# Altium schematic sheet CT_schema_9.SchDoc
size 390 x 385 mm
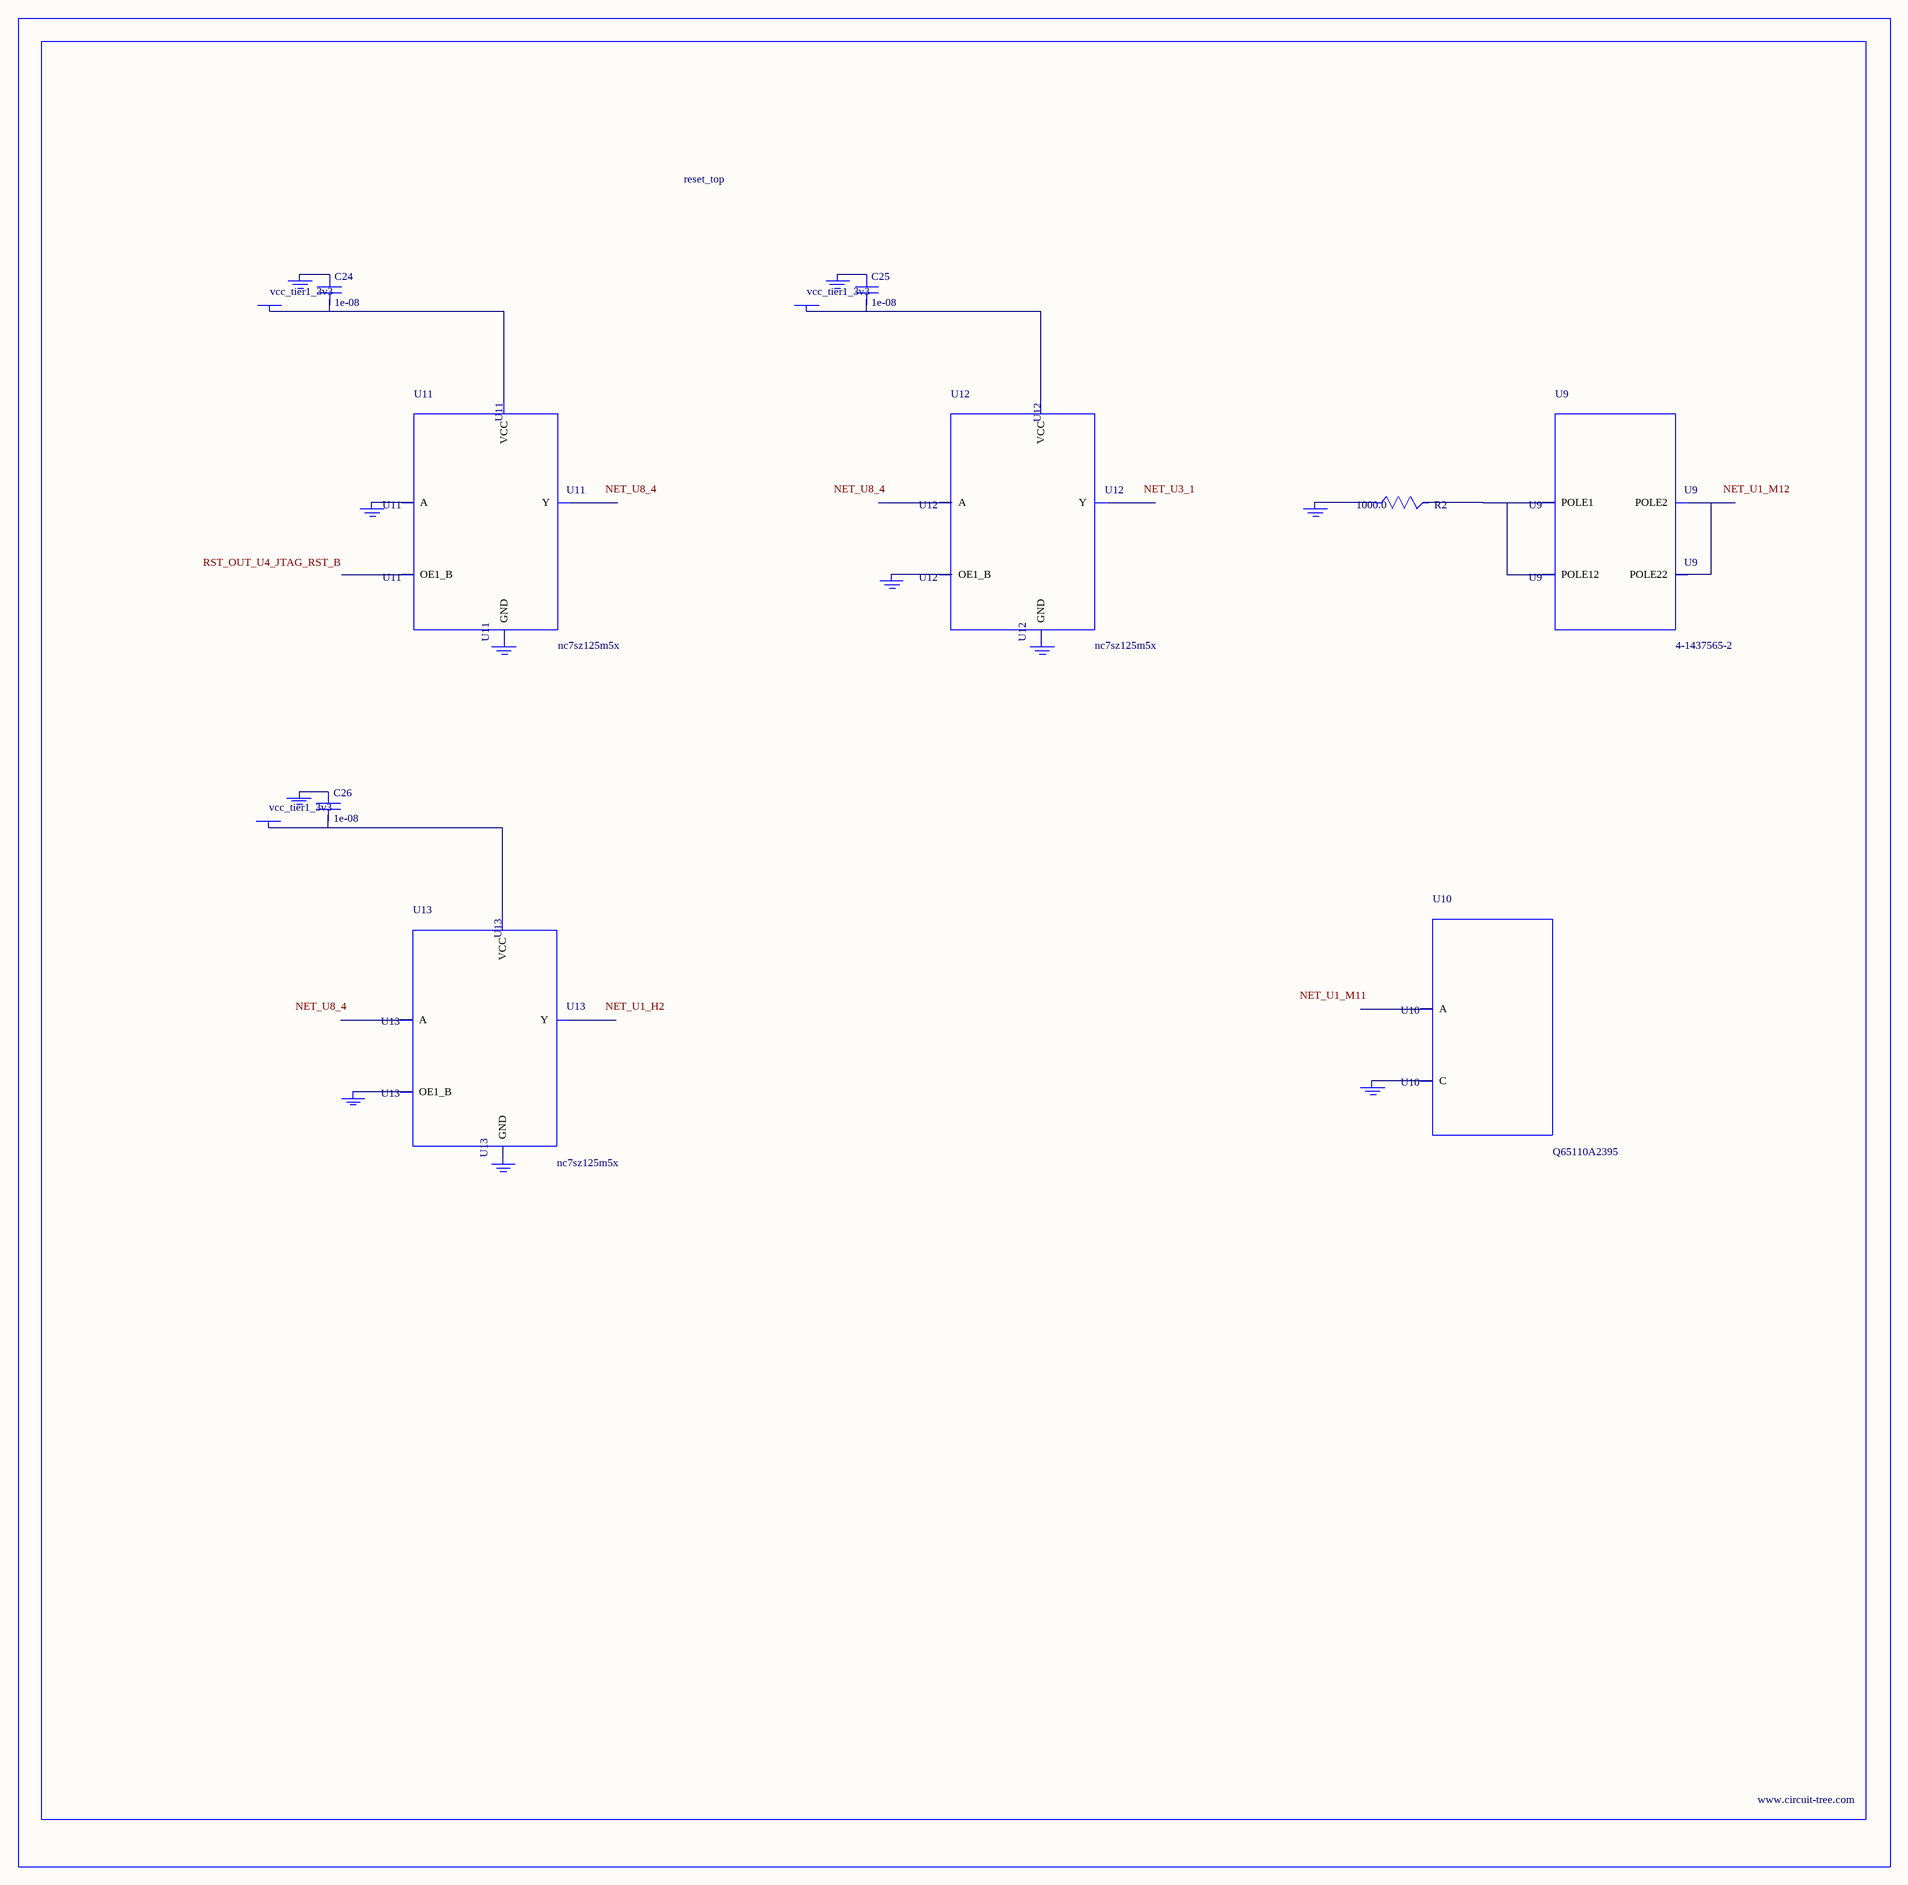
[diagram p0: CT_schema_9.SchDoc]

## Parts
BORDER8  (no value)
C24  1e-08  [C0402]
C25  1e-08  [C0402]
C26  1e-08  [C0402]
GND_INSTANCE_8_0  (no value)
GND_INSTANCE_8_1  (no value)
GND_INSTANCE_8_2  (no value)
GND_INSTANCE_8_3  (no value)
GND_INSTANCE_8_4  (no value)
GND_INSTANCE_8_5  (no value)
GND_INSTANCE_8_6  (no value)
GND_INSTANCE_8_7  (no value)
GND_INSTANCE_8_8  (no value)
GND_INSTANCE_8_9  (no value)
GND_INSTANCE_8_10  (no value)
POWER_INSTANCE_8_0  vcc_tier1_3v3
POWER_INSTANCE_8_1  vcc_tier1_3v3
POWER_INSTANCE_8_2  vcc_tier1_3v3
R2  1000.0  [R0603]
U9  4-1437565-2  [SW_4-1437565-2]
U10  Q65110A2395  [LGM67K-G1J2-24-Z]
U11  nc7sz125m5x  [NC7SZ125M5X]
U12  nc7sz125m5x  [NC7SZ125M5X]
U13  nc7sz125m5x  [NC7SZ125M5X]

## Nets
NetC24_1: C24.1 GND_INSTANCE_8_2.0(GND)
NetC24_2: C24.2 POWER_INSTANCE_8_0.0(PWR) U11.5(VCC)
NetC25_1: C25.1 GND_INSTANCE_8_5.0(GND)
NetC25_2: C25.2 POWER_INSTANCE_8_1.0(PWR) U12.5(VCC)
NetC26_1: C26.1 GND_INSTANCE_8_8.0(GND)
NetC26_2: C26.2 POWER_INSTANCE_8_2.0(PWR) U13.5(VCC)
NetGND_INSTANCE_8_0_0: GND_INSTANCE_8_0.0(GND) R2.1
NetGND_INSTANCE_8_1_0: GND_INSTANCE_8_1.0(GND) U10.C
NetGND_INSTANCE_8_3_0: GND_INSTANCE_8_3.0(GND) U11.2(A)
NetGND_INSTANCE_8_4_0: GND_INSTANCE_8_4.0(GND) U11.3(GND)
NetGND_INSTANCE_8_6_0: GND_INSTANCE_8_6.0(GND) U12.1(OE1_B)
NetGND_INSTANCE_8_7_0: GND_INSTANCE_8_7.0(GND) U12.3(GND)
NetGND_INSTANCE_8_9_0: GND_INSTANCE_8_9.0(GND) U13.1(OE1_B)
NetGND_INSTANCE_8_10_0: GND_INSTANCE_8_10.0(GND) U13.3(GND)
NetR2_2: R2.2 U9.1(POLE1) U9.2(POLE12)
NetU9_3: U9.3(POLE2) U9.4(POLE22)

Not connected (* = marked no-connect by the designer): U10 A; U11 1(OE1_B) 4(Y); U12 2(A) 4(Y); U13 2(A) 4(Y)

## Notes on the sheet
- Labels drawn without touching a wire or pin: NET_U1_H2, NET_U1_M11, NET_U1_M12, NET_U3_1, NET_U8_4, RST_OUT_U4_JTAG_RST_B

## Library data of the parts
BORDER8 = BORDER_PAGE8
C24-C26 = C0402C103K3RAC
GND_INSTANCE_8_0-GND_INSTANCE_8_10 = GND
POWER_INSTANCE_8_0-POWER_INSTANCE_8_2 = PWR
R2 = RC0603JR-071KL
